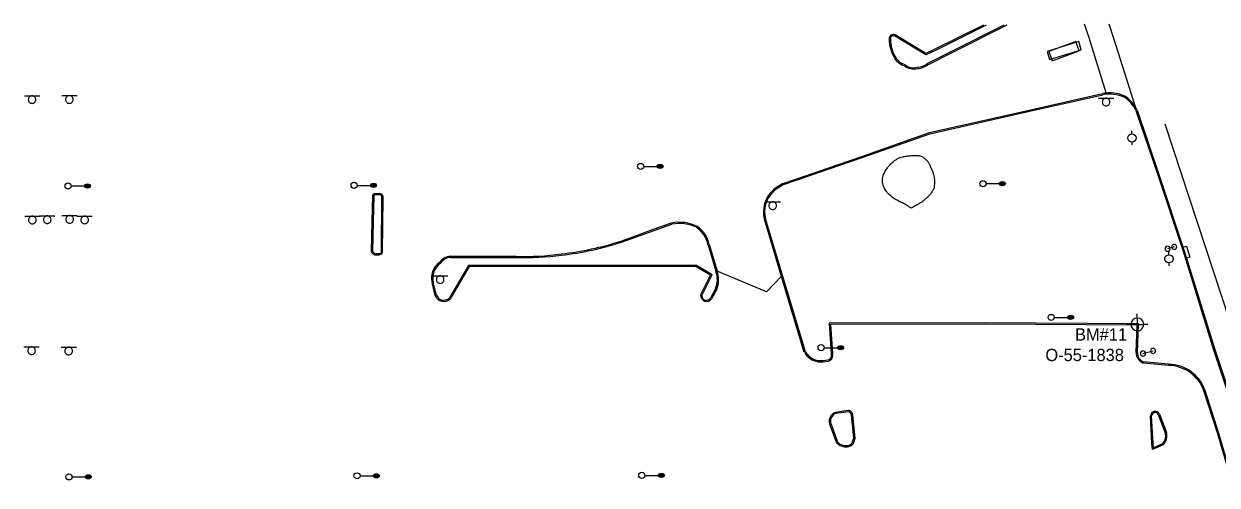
# Model space of a CAD drawing. Extents: x 2145380 to 2157287, y 139568 to 149130.
# Drawn here: x 2146561 to 2147143, y 143433 to 143659 of the extents above; entities that cross this region are included whole.
import ezdxf

# ---------------------------------------------------------------- set-up
doc = ezdxf.new("R2010")
doc.units = 0
for name, color, linetype in [('SURV_Benchmark', 7, 'Continuous'), ('TOPO_Asphalt', 7, 'Continuous'), ('TOPO_Curb Back', 7, 'Continuous'), ('TOPO_DRAIN_Inlet Grate', 7, 'Continuous'), ('TOPO_Light Pole', 7, 'Continuous'), ('TOPO_Misc', 7, 'Continuous'), ('TOPO_Misc Line', 7, 'Continuous'), ('TOPO_Power Pole', 7, 'Continuous'), ('TOPO_Sign', 7, 'Continuous'), ('TOPO_Tree Line', 7, 'Continuous'), ('TOPO_Wall Freestanding', 7, 'Continuous')]:
    doc.layers.add(name, color=color, linetype=linetype)

# ---------------------------------------------------------------- blocks, each defined once
blk = doc.blocks.new('LP')
at = {"layer": 'TOPO_Light Pole'}
blk.add_line((3.8, 0), (20.3, 0), dxfattribs=at)
for points in [[(20.3, 0), (27.9, 0)], [(20.3, 0), (23.5, 0)], [(20.8, 1.3), (27.4, 1.3)], [(20.8, 1.3), (23.5, 1.3)], [(23.7, 1.3), (27.4, 1.3)], [(23.7, 0), (27.9, 0)], [(20.8, -1.3), (27.4, -1.3)], [(20.8, -1.3), (23.5, -1.3)], [(23.7, -1.3), (27.4, -1.3)]]:
    blk.add_lwpolyline(points, dxfattribs=at)
blk.add_circle((0, 0), 3.81, dxfattribs=at)
blk.add_ellipse((24.1, 0), major_axis=(3.81, 0), ratio=0.666667, dxfattribs=at)
blk = doc.blocks.new('POWPOL')
at = {"layer": 'TOPO_Power Pole'}
for p, q in [((0, 10.2), (0, 17.3)), ((0, -10.2), (0, -17.3))]:
    blk.add_line(p, q, dxfattribs=at)
blk.add_circle((0, 0), 10.2, dxfattribs=at)
blk = doc.blocks.new('POST')
at = {"layer": 'TOPO_Misc'}
for start, end in [(90, 180), (180, 270), (360, 90), (270, 0)]:
    blk.add_arc((0, 0), 3.16, start, end, dxfattribs=at)
blk = doc.blocks.new('BM')
at = {"layer": 'SURV_Benchmark'}
for p, q in [((-2.49, 0), (-4.16, 0)), ((0, 2.49), (0, 4.15)), ((4.16, 0), (2.49, 0)), ((0, -4.16), (0, -2.49))]:
    blk.add_line(p, q, dxfattribs=at)
for points in [[(-2.5, 0), (-2.49, 0), (0, 0), (0, -2.49), (0, -2.49)], [(-2.5, 0), (-2.49, 0), (0, 0), (0, -2.49), (0, -2.49)], [(0, 2.49), (0, 2.49), (0, 0), (2.49, 0), (2.49, 0), (2.49, 0)], [(0, 2.49), (0, 2.49), (0, 0), (2.49, 0), (2.49, 0), (2.49, 0), (2.49, 0)]]:
    blk.add_lwpolyline(points, dxfattribs=at)
for start, end in [(90.0638, 180.0068), (0.0638, 90.0068), (0.0638, 90.0068), (180.0638, 270.0068), (180.0638, 270.0068), (269.9472, 359.9927)]:
    blk.add_arc((0, 0), 2.5, start, end, dxfattribs=at)

msp = doc.modelspace()

# ---------------------------------------------------------------- linework, layer by layer
at = {"layer": 'TOPO_Asphalt'}
for points in [[(2147089.23, 143624.76), (2147081.01, 143651.78), (2147078.72, 143658.44)], [(2147090.55, 143658.55), (2147092.96, 143651.13), (2147103.4, 143618.09)], [(2146930.6, 143535.14), (2146923.4, 143527.56), (2146899.27, 143537.66)]]:
    msp.add_lwpolyline(points, dxfattribs=at)
at = {"layer": 'TOPO_Curb Back'}
for p, q in [((2146963.26, 143469.52), (2146957.1, 143468.61)), ((2146963.29, 143468.92), (2146957.24, 143468.02)), ((2146955.01, 143462.34), (2146958.09, 143454.12)), ((2146966.02, 143456.14), (2146964.82, 143467.23)), ((2146966.63, 143456.08), (2146965.43, 143467.25)), ((2147111.52, 143453.34), (2147110.85, 143466.87)), ((2147112.12, 143453.38), (2147111.45, 143466.88)), ((2147114.7, 143467.53), (2147118.11, 143458.6)), ((2147115.25, 143467.77), (2147118.67, 143458.79)), ((2146954.46, 143462.09), (2146957.57, 143453.8)), ((2146965.24, 143453.7), (2146966.02, 143456.14)), ((2146965.78, 143453.42), (2146966.63, 143456.08)), ((2147111.84, 143450.45), (2147111.52, 143453.34)), ((2147117.1, 143452.79), (2147111.84, 143450.45)), ((2147112.34, 143451.34), (2147112.12, 143453.38)), ((2147116.76, 143453.3), (2147112.34, 143451.34))]:
    msp.add_line(p, q, dxfattribs=at)
for points in [[(2147030.68, 143657.98), (2147005.21, 143645.27), (2147001.09, 143643.41), (2146985.88, 143652.65)], [(2147029.31, 143657.97), (2147004.95, 143645.81), (2147001.13, 143644.09), (2146986.15, 143653.19)], [(2147002.17, 143639.25), (2147013.8, 143645.12), (2147039.46, 143658.07)], [(2147002.49, 143638.73), (2147014.07, 143644.59), (2147040.81, 143658.08)], [(2146931.88, 143580.74), (2146969.87, 143593.74), (2147002.94, 143605.38), (2147051.67, 143616.42), (2147087.51, 143624.51)], [(2146932.12, 143580.19), (2146970.07, 143593.18), (2147003.11, 143604.8), (2147051.81, 143615.83), (2147087.62, 143623.92)], [(2147103.78, 143616.14), (2147114.24, 143585.18), (2147126.8, 143547.4), (2147141.7, 143499.15), (2147161.24, 143440.63), (2147180.64, 143382.35), (2147196.74, 143332.44), (2147212.6, 143285.35), (2147225.45, 143246.61), (2147229.49, 143234.16)], [(2147104.33, 143616.36), (2147114.81, 143585.37), (2147127.37, 143547.58), (2147142.27, 143499.34), (2147161.81, 143440.82), (2147181.21, 143382.54), (2147197.31, 143332.63), (2147213.16, 143285.54), (2147226.02, 143246.79), (2147230.07, 143234.33)], [(2146730.87, 143574.5), (2146730.61, 143562.01), (2146730.31, 143547.27)], [(2146731.47, 143574.46), (2146731.21, 143562), (2146730.92, 143547.41)], [(2146734.54, 143574.91), (2146732.09, 143574.91)], [(2146734.56, 143575.51), (2146732.13, 143575.51)], [(2146735.25, 143546.83), (2146735.47, 143573.62)], [(2146735.85, 143546.83), (2146736.07, 143573.55)], [(2146941.81, 143498.04), (2146932.77, 143527.82), (2146922.31, 143563.02)], [(2146942.37, 143498.27), (2146933.35, 143527.99), (2146922.89, 143563.19)], [(2146852.28, 143552.38), (2146868.22, 143558.16), (2146876.99, 143561.19)], [(2146852.47, 143551.82), (2146868.42, 143557.6), (2146877.14, 143560.61)], [(2146894.76, 143550.48), (2146898.64, 143537.63)], [(2146895.34, 143550.63), (2146899.21, 143537.81)], [(2146732.06, 143545.61), (2146734.14, 143545.65)], [(2146732.18, 143546.21), (2146734.09, 143546.25)], [(2146768.93, 143544.98), (2146801.07, 143544.9)], [(2146768.93, 143544.38), (2146801.06, 143544.3)], [(2146891.74, 143525.71), (2146896.84, 143535.91), (2146889.08, 143540.44), (2146835.19, 143540.47), (2146777.78, 143540.48), (2146768.42, 143524.54)], [(2146891.14, 143525.85), (2146896.06, 143535.67), (2146888.91, 143539.84), (2146835.19, 143539.87), (2146778.12, 143539.88), (2146768.9, 143524.18)], [(2146761.56, 143525.79), (2146759.99, 143532.07)], [(2146762.14, 143525.96), (2146760.57, 143532.21)], [(2146898.47, 143529.03), (2146896, 143524.5)], [(2146899.01, 143528.78), (2146896.52, 143524.19)], [(2147104.53, 143497.86), (2147104.98, 143511.85), (2147030.09, 143512.41), (2146953.93, 143512.25), (2146954.98, 143497.25)], [(2147103.93, 143497.88), (2147104.36, 143511.25), (2147030.09, 143511.81), (2146954.57, 143511.65), (2146955.58, 143497.36)], [(2147119.63, 143491.57), (2147107.32, 143492.74)], [(2147119.67, 143492.17), (2147107.46, 143493.33)], [(2147167.49, 143264.93), (2147164.49, 143319.81), (2147161.9, 143366.93), (2147159.96, 143402.77), (2147143.75, 143458.08), (2147136.94, 143479.1)], [(2147168.09, 143264.97), (2147165.09, 143319.84), (2147162.5, 143366.96), (2147160.55, 143402.87), (2147144.33, 143458.26), (2147137.51, 143479.29)]]:
    msp.add_lwpolyline(points, dxfattribs=at)
for centre, radius, start, end in [((2146985.33, 143651.26), 2.1, 67.17467, 186.56015), ((2147001.57, 143651.25), 18.32, 180.7114, 208.65164), ((2146985.33, 143651.26), 1.5, 68.73166, 187.64463), ((2147001.57, 143651.25), 17.72, 180.60474, 208.68308), ((2146993.32, 143646.42), 8.77, 206.81186, 251.47061), ((2146993.32, 143646.42), 8.17, 206.74494, 252.21681), ((2146995.19, 143643.95), 7.47, 231.4433, 284.67141), ((2146995.19, 143643.95), 6.87, 230.56163, 285.12877), ((2146996.33, 143646.99), 9.7, 273.83834, 307.01333), ((2146996.33, 143646.99), 10.3, 274.16609, 306.71117), ((2147090.77, 143606.41), 18.39, 65.81215, 100.22229), ((2147090.77, 143606.41), 17.79, 65.94422, 100.18041), ((2147089.83, 143609.62), 15.4, 25.04762, 57.85188), ((2147089.83, 143609.62), 16, 24.92676, 58.00408), ((2146949.48, 143548.26), 36.94, 118.44754, 129.00196), ((2146949.48, 143548.26), 36.34, 118.52628, 128.96493), ((2146731.99, 143574.39), 1.13, 83.02433, 174.68125), ((2146731.99, 143574.39), 0.528, 79.79373, 172.77657), ((2146734.45, 143573.86), 1.05, 346.45627, 85.01372), ((2146734.45, 143573.86), 1.65, 349.10762, 86.02255), ((2146935.93, 143566.72), 14.11, 133.45526, 195.19414), ((2146935.93, 143566.72), 13.51, 133.55351, 195.1644), ((2146880.71, 143541.89), 19.65, 63.31911, 100.90496), ((2146880.71, 143541.89), 19.05, 63.44204, 100.77772), ((2146881.62, 143547.92), 13.38, 11.03675, 55.37477), ((2146881.62, 143547.92), 13.98, 11.16241, 55.54867), ((2146806.51, 143693.13), 148, 276.44592, 288.0147), ((2146806.51, 143693.13), 148.6, 276.4484, 288.01857), ((2146733.48, 143548.85), 3.54, 206.59099, 246.32884), ((2146733.48, 143548.85), 2.94, 209.3553, 243.88186), ((2146733.83, 143548.03), 1.8, 278.53799, 325.30791), ((2146733.83, 143548.03), 2.4, 277.52859, 325.30791), ((2146769.41, 143537.97), 7.02, 94.10884, 146.57125), ((2146769.41, 143537.97), 6.42, 94.10884, 147.56049), ((2146804.9, 143681.27), 137.03, 268.39416, 277.67267), ((2146804.9, 143681.27), 136.43, 268.39095, 277.67536), ((2146768.9, 143534.35), 9.2, 125.54292, 194.40606), ((2146768.9, 143534.35), 8.6, 124.7958, 194.41869), ((2146887.22, 143533.56), 12.12, 338.04578, 19.57876), ((2146887.22, 143533.56), 12.72, 337.88853, 19.51306), ((2146765.72, 143527.2), 4.39, 198.83843, 316.42691), ((2146765.72, 143527.2), 3.79, 199.20461, 315.4214), ((2146894.06, 143525.75), 2.91, 178.09489, 327.65735), ((2146894.06, 143525.75), 2.31, 181.16529, 327.1922), ((2146949.85, 143502.42), 9.15, 208.57677, 261.72216), ((2146949.85, 143502.42), 8.55, 208.98154, 261.56888), ((2146952.79, 143496.5), 2.92, 285.21845, 17.21296), ((2147109.19, 143497.66), 5.27, 177.61285, 249.18205), ((2147109.19, 143497.66), 4.67, 177.57905, 248.21727), ((2146949.84, 143512.65), 19.34, 266.12819, 281.08649), ((2146949.84, 143512.65), 18.74, 266.19941, 281.01702), ((2146952.79, 143496.5), 2.32, 285.72661, 18.82742), ((2147119.4, 143472.99), 18.58, 19.19219, 89.27969), ((2147119.4, 143472.99), 19.18, 19.17267, 89.20526), ((2146958.48, 143464.26), 4.57, 107.64721, 208.25442), ((2146963.22, 143467.31), 2.21, 358.40082, 88.93476), ((2146963.22, 143467.31), 1.61, 357.07105, 87.30125), ((2147113.16, 143466.8), 2.31, 24.71511, 178.2287), ((2147113.16, 143466.8), 1.71, 25.33708, 177.4816), ((2146958.48, 143464.26), 3.97, 108.3207, 208.81532), ((2147113.02, 143457.07), 5.31, 314.71584, 16.70322), ((2147113.02, 143457.07), 5.91, 313.62316, 16.92164), ((2146962.21, 143458.02), 6.27, 222.2905, 274.31108), ((2146962.21, 143458.02), 5.67, 223.42444, 274.35927), ((2146962.44, 143455.93), 3.58, 273.33748, 321.43467), ((2146962.44, 143455.93), 4.18, 273.41183, 323.00096)]:
    msp.add_arc(centre, radius, start, end, dxfattribs=at)
at = {"layer": 'TOPO_DRAIN_Inlet Grate'}
msp.add_lwpolyline([(2147126.79, 143549.34), (2147128.45, 143549.91), (2147130.02, 143544.47), (2147128.48, 143543.99)], dxfattribs=at)
at = {"layer": 'TOPO_Misc Line'}
msp.add_lwpolyline([(2147242.33, 143232.97), (2147210.41, 143329.68), (2147184.07, 143408.45), (2147169.19, 143453.56), (2147149.47, 143513.78), (2147117.99, 143609.55)], dxfattribs=at)
at = {"layer": 'TOPO_Sign'}
msp.add_lwpolyline([(2147061.59, 143641.05), (2147077.08, 143645.92), (2147075.85, 143649.85), (2147060.36, 143644.99)], close=True, dxfattribs=at)
for points in [[(2146560.89, 143623.4), (2146568.39, 143623.41)], [(2146562.78, 143621.54), (2146562.78, 143621.54)], [(2146564.64, 143623.4), (2146564.64, 143623.4)], [(2146564.64, 143619.67), (2146564.64, 143619.67)], [(2146566.51, 143621.54), (2146566.51, 143621.54)], [(2146579.09, 143623.44), (2146586.58, 143623.45)], [(2146580.97, 143621.57), (2146580.97, 143621.57)], [(2146582.84, 143623.44), (2146582.84, 143623.44)], [(2146582.84, 143619.71), (2146582.84, 143619.71)], [(2146584.7, 143621.57), (2146584.7, 143621.57)], [(2147085.46, 143622.18), (2147092.95, 143622.19)], [(2147087.34, 143620.32), (2147087.34, 143620.32)], [(2147089.21, 143622.18), (2147089.21, 143622.18)], [(2147091.08, 143620.32), (2147091.08, 143620.32)], [(2147089.21, 143618.45), (2147089.21, 143618.45)], [(2146922.62, 143571.53), (2146930.12, 143571.54)], [(2146924.51, 143569.66), (2146924.51, 143569.66)], [(2146926.37, 143571.53), (2146926.37, 143571.53)], [(2146926.37, 143567.8), (2146926.37, 143567.8)], [(2146928.24, 143569.66), (2146928.24, 143569.66)], [(2146561.03, 143564.54), (2146568.52, 143564.55)], [(2146562.91, 143562.68), (2146562.91, 143562.68)], [(2146564.78, 143564.54), (2146564.78, 143564.54)], [(2146566.64, 143562.68), (2146566.64, 143562.68)], [(2146568.26, 143564.65), (2146575.76, 143564.65)], [(2146570.15, 143562.78), (2146570.15, 143562.78)], [(2146572.01, 143564.65), (2146572.01, 143564.65)], [(2146573.88, 143562.78), (2146573.88, 143562.78)], [(2146579.22, 143564.83), (2146586.72, 143564.83)], [(2146581.11, 143562.96), (2146581.11, 143562.96)], [(2146582.97, 143564.83), (2146582.97, 143564.83)], [(2146584.84, 143562.96), (2146584.84, 143562.96)], [(2146586.54, 143564.58), (2146594.03, 143564.59)], [(2146588.42, 143562.71), (2146588.42, 143562.71)], [(2146590.29, 143564.58), (2146590.29, 143564.58)], [(2146592.16, 143562.71), (2146592.16, 143562.71)], [(2146564.78, 143560.81), (2146564.78, 143560.81)], [(2146572.01, 143560.91), (2146572.01, 143560.91)], [(2146582.97, 143561.09), (2146582.97, 143561.09)], [(2146590.29, 143560.84), (2146590.29, 143560.84)], [(2147122.45, 143549.51), (2147119.23, 143548.61)], [(2146760.19, 143535.41), (2146767.68, 143535.41)], [(2146762.07, 143533.54), (2146762.07, 143533.54)], [(2146763.94, 143535.41), (2146763.94, 143535.41)], [(2146765.81, 143533.54), (2146765.81, 143533.54)], [(2146763.94, 143531.67), (2146763.94, 143531.67)], [(2146560.61, 143500.63), (2146568.1, 143500.64)], [(2146562.49, 143498.76), (2146562.49, 143498.76)], [(2146564.36, 143500.63), (2146564.36, 143500.63)], [(2146566.23, 143498.76), (2146566.23, 143498.76)], [(2146578.77, 143500.5), (2146586.26, 143500.51)], [(2146580.65, 143498.63), (2146580.65, 143498.63)], [(2146582.52, 143500.5), (2146582.52, 143500.5)], [(2146584.39, 143498.63), (2146584.39, 143498.63)], [(2147107.22, 143497.41), (2147112.13, 143498.68)], [(2146564.36, 143496.89), (2146564.36, 143496.89)], [(2146582.52, 143496.77), (2146582.52, 143496.77)]]:
    msp.add_lwpolyline(points, dxfattribs=at)
for centre, start, end in [((2146564.64, 143621.54), 89.99996, 180.00004), ((2146564.64, 143621.54), 179.99996, 270.00004), ((2146564.64, 143621.54), 359.99996, 90.00004), ((2146564.64, 143621.54), 269.99996, 0.00004), ((2146582.84, 143621.57), 89.99996, 180.00004), ((2146582.84, 143621.57), 179.99996, 270.00004), ((2146582.84, 143621.57), 359.99996, 90.00004), ((2146582.84, 143621.57), 269.99996, 0.00004), ((2147089.21, 143620.32), 89.99996, 180.00004), ((2147089.21, 143620.32), 179.99996, 270.00004), ((2147089.21, 143620.32), 359.99996, 90.00004), ((2147089.21, 143620.32), 269.99996, 0.00004), ((2146926.37, 143569.66), 89.99996, 180.00004), ((2146926.37, 143569.66), 179.99996, 270.00004), ((2146926.37, 143569.66), 359.99996, 90.00004), ((2146926.37, 143569.66), 269.99996, 0.00004), ((2146564.78, 143562.68), 89.99996, 180.00004), ((2146564.78, 143562.68), 179.99996, 270.00004), ((2146564.78, 143562.68), 359.99996, 90.00004), ((2146564.78, 143562.68), 269.99996, 0.00004), ((2146572.01, 143562.78), 89.99996, 180.00004), ((2146572.01, 143562.78), 179.99996, 270.00004), ((2146572.01, 143562.78), 359.99996, 90.00004), ((2146572.01, 143562.78), 269.99996, 0.00004), ((2146582.97, 143562.96), 89.99996, 180.00004), ((2146582.97, 143562.96), 179.99996, 270.00004), ((2146582.97, 143562.96), 359.99996, 90.00004), ((2146582.97, 143562.96), 269.99996, 0.00004), ((2146590.29, 143562.71), 89.99996, 180.00004), ((2146590.29, 143562.71), 179.99996, 270.00004), ((2146590.29, 143562.71), 359.99996, 90.00004), ((2146590.29, 143562.71), 269.99996, 0.00004), ((2146763.94, 143533.54), 89.99996, 180.00004), ((2146763.94, 143533.54), 179.99996, 270.00004), ((2146763.94, 143533.54), 359.99996, 90.00004), ((2146763.94, 143533.54), 269.99996, 0.00004), ((2146564.36, 143498.76), 89.99996, 180.00004), ((2146564.36, 143498.76), 179.99996, 270.00004), ((2146564.36, 143498.76), 359.99996, 90.00004), ((2146564.36, 143498.76), 269.99996, 0.00004), ((2146582.52, 143498.63), 89.99996, 180.00004), ((2146582.52, 143498.63), 179.99996, 270.00004), ((2146582.52, 143498.63), 359.99996, 90.00004), ((2146582.52, 143498.63), 269.99996, 0.00004)]:
    msp.add_arc(centre, 1.87, start, end, dxfattribs=at)
at = {"layer": 'TOPO_Tree Line'}
msp.add_open_spline([(2146994.02, 143568.44), (2146995.38, 143569.21), (2146996.74, 143569.97), (2146998.1, 143570.73), (2146999.17, 143571.33), (2147000.04, 143572.19), (2147000.98, 143572.99), (2147002.21, 143574.05), (2147003.31, 143575.05), (2147004.23, 143576.54), (2147005.1, 143577.97), (2147005.31, 143579.48), (2147005.34, 143580.99), (2147005.36, 143582.28), (2147005.24, 143583.59), (2147004.89, 143584.88), (2147004.46, 143586.48), (2147003.86, 143587.94), (2147003.08, 143589.43), (2147002.41, 143590.71), (2147001.74, 143591.82), (2147000.49, 143592.76), (2146999.16, 143593.75), (2146997.73, 143594.19), (2146996.23, 143594.22), (2146995.11, 143594.23), (2146993.98, 143594.16), (2146992.87, 143594.03), (2146991.91, 143593.91), (2146990.97, 143593.78), (2146990.03, 143593.55), (2146988.52, 143593.18), (2146987.13, 143592.54), (2146985.83, 143591.64), (2146984.93, 143591.01), (2146984.19, 143590.3), (2146983.48, 143589.49), (2146982.87, 143588.81), (2146982.35, 143588.11), (2146981.84, 143587.35), (2146981.2, 143586.39), (2146980.72, 143585.38), (2146980.35, 143584.31), (2146979.91, 143583.01), (2146979.9, 143581.55), (2146980.22, 143580.24), (2146980.5, 143579.11), (2146980.94, 143578.02), (2146981.64, 143577.03), (2146982.19, 143576.26), (2146982.76, 143575.61), (2146983.43, 143574.97), (2146984.15, 143574.29), (2146984.84, 143573.56), (2146985.71, 143573.09), (2146986.69, 143572.55), (2146987.67, 143572.03), (2146988.65, 143571.51), (2146989.68, 143570.96), (2146990.76, 143570.5), (2146991.75, 143569.87), (2146992.5, 143569.4), (2146993.26, 143568.92), (2146994.02, 143568.44)], degree=3, dxfattribs=at)
at = {"layer": 'TOPO_Wall Freestanding'}
msp.add_lwpolyline([(2147062.93, 143640.48), (2147076.05, 143645.4), (2147074.35, 143649.95), (2147061.22, 143645.03)], close=True, dxfattribs=at)

# ---------------------------------------------------------------- block references
at = {"layer": 'SURV_Benchmark', "xscale": 1.25, "yscale": 1.25}
msp.add_blockref('BM', (2147104.44, 143511.6), dxfattribs=at)
at = {"layer": 'TOPO_Light Pole', "xscale": 0.39370000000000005, "yscale": 0.3937000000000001}
for p in [(2146861.88, 143588.84), (2146582.2, 143579.29), (2146721.89, 143579.59), (2147029.01, 143580.43), (2147062.37, 143515.02), (2146950.02, 143500.21), (2146723.33, 143437.59), (2146862.43, 143437.8), (2146582.59, 143437.09)]:
    msp.add_blockref('LP', p, dxfattribs=at)
at = {"layer": 'TOPO_Misc', "xscale": 0.39370000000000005, "yscale": 0.3937000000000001}
for p in [(2147119.23, 143548.61), (2147122.45, 143549.51), (2147107.22, 143497.41), (2147112.13, 143498.68)]:
    msp.add_blockref('POST', p, dxfattribs=at)
at = {"layer": 'TOPO_Power Pole', "xscale": 0.19685000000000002, "yscale": 0.19685000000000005}
for p in [(2147101.8, 143602.77), (2147119.88, 143543.67)]:
    msp.add_blockref('POWPOL', p, dxfattribs=at)

# ---------------------------------------------------------------- texts
at = {"layer": 'SURV_Benchmark'}
for s, p in [('BM#11', (2147074.03, 143503.71)), ('O-55-1838', (2147059.54, 143493.68))]:
    msp.add_text(s, height=6, dxfattribs=at).set_placement(p)

doc.saveas('drawing.dxf')
